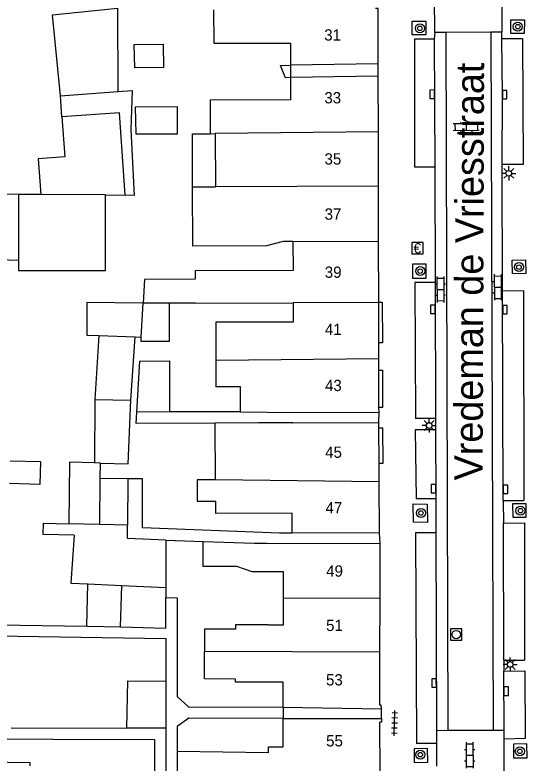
# Model space of a CAD drawing. Extents: x 132998 to 136004, y 396998 to 398512.
# Drawn here: x 133210.3 to 133255.7, y 397420.4 to 397486.6 of the extents above; entities that cross this region are included whole.
import ezdxf

# ---------------------------------------------------------------- set-up
doc = ezdxf.new("R2010")
doc.units = 0
for name, color, linetype in [('gg-afsc-erfafscheiding', 7, 'Continuous'), ('gg-anno-huisnummerreeks BGT', 7, 'Continuous'), ('gg-anno-openbare ruimte label', 7, 'Continuous'), ('gg-bbg-gedigitaliseerde bebouwing', 7, 'Continuous'), ('gg-bbg-gedigitaliseerde bebouwing onder overbouw', 7, 'Continuous'), ('gg-bbg-gedigitaliseerde bijgebouw', 7, 'Continuous'), ('gg-bbg-gedigitaliseerde overbouw', 7, 'Continuous'), ('gg-bbg-hoofdgebouw', 7, 'Continuous'), ('gg-bbg-luifel en loopbrug', 7, 'Continuous'), ('gg-bbg-onder overbouw', 7, 'Continuous'), ('gg-bbg-pand overbouw', 7, 'Continuous'), ('gg-bbg-tussenscheiding', 7, 'Continuous'), ('gg-knt-verharding', 7, 'Continuous'), ('gg-knt-verharding nz', 7, 'Continuous'), ('gt-grn-weggrens', 7, 'Continuous'), ('gt-symb-betaalautomaat', 7, 'Continuous'), ('gt-symb-boom', 7, 'Continuous'), ('gt-symb-klinker verharding', 7, 'Continuous'), ('gt-symb-kolk', 7, 'Continuous'), ('gt-symb-lichtmast', 7, 'Continuous'), ('gt-symb-rioolschacht', 7, 'Continuous'), ('gt-symb-tegel verharding', 7, 'Continuous')]:
    doc.layers.add(name, color=color, linetype=linetype)

# ---------------------------------------------------------------- blocks, each defined once
blk = doc.blocks.new('gt0-BOOM')
at = {"layer": 'gt-symb-boom'}
for radius in [0.4, 0.2]:
    blk.add_circle((0, 0), radius, dxfattribs=at)
blk = doc.blocks.new('gt0-KOLK')
at = {"layer": 'gt-symb-kolk'}
blk.add_lwpolyline([(0, 0), (0.375, 0), (0.375, 0.4), (-0.375, 0.4), (-0.375, 0), (0, 0)], dxfattribs=at)
blk = doc.blocks.new('gt0-KL1')
at = {"layer": 'gt-symb-klinker verharding'}
for p, q in [((-1.15, 0.3), (1.15, 0.3)), ((-1, -0.3), (-1, 0.3)), ((-0.5, 0.3), (-0.5, 0.45)), ((0, -0.3), (0, 0.3)), ((0.5, 0.3), (0.5, 0.45)), ((1, -0.3), (1, 0.3)), ((-1.15, -0.3), (1.15, -0.3)), ((-0.5, -0.45), (-0.5, -0.3)), ((0.5, -0.45), (0.5, -0.3))]:
    blk.add_line(p, q, dxfattribs=at)
blk = doc.blocks.new('gt0-BA')
at = {"layer": 'gt-symb-betaalautomaat'}
blk.add_lwpolyline([(-0.498, -0.507), (0.502, -0.507), (0.502, 0.493), (-0.498, 0.493)], close=True, dxfattribs=at)
blk.add_text('€', height=0.9, dxfattribs=at).set_placement((-0.357, -0.457))
blk = doc.blocks.new('gt0-LMAST')
at = {"layer": 'gt-symb-lichtmast'}
for p, q in [((-0.182, 0.173), (-0.447, 0.438)), ((-0.005, 0.246), (-0.005, 0.621)), ((0.172, 0.173), (0.437, 0.438)), ((-0.255, -0.004), (-0.63, -0.004)), ((-0.182, -0.181), (-0.447, -0.446)), ((-0.005, -0.254), (-0.005, -0.629)), ((0.437, -0.446), (0.172, -0.181)), ((0.245, -0.004), (0.62, -0.004))]:
    blk.add_line(p, q, dxfattribs=at)
blk.add_circle((-0.005, -0.004), 0.25, dxfattribs=at)
blk = doc.blocks.new('gt0-RS')
at = {"layer": 'gt-symb-rioolschacht'}
blk.add_lwpolyline([(-0.5, -0.5), (0.5, -0.5), (0.5, 0.5), (-0.5, 0.5)], close=True, dxfattribs=at)
blk.add_circle((0, 0), 0.375, dxfattribs=at)
blk = doc.blocks.new('gt0-TEG1')
at = {"layer": 'gt-symb-tegel verharding'}
for p, q in [((-1.125, 0), (1.125, 0)), ((-0.9, -0.25), (-0.9, 0.25)), ((-0.45, -0.25), (-0.45, 0.25)), ((0, -0.25), (0, 0.25)), ((0.45, -0.25), (0.45, 0.25)), ((0.9, -0.25), (0.9, 0.25))]:
    blk.add_line(p, q, dxfattribs=at)

msp = doc.modelspace()

# ---------------------------------------------------------------- linework, layer by layer
at = {"layer": 'gg-afsc-erfafscheiding'}
for p, q in [((133230.329, 397451.525), (133224.045, 397451.503)), ((133223.706, 397440.171), (133227.008, 397440.044)), ((133195.513, 397432.894), (133216.706, 397432.535)), ((133210.012, 397423.555), (133220.258, 397423.523)), ((133223.702, 397423.512), (133223.732, 397413.948))]:
    msp.add_line(p, q, dxfattribs=at)
for points in [[(133234.752, 397481.096), (133234.315, 397481.089), (133233.877, 397482.17), (133234.75, 397482.184)], [(133228.086, 397450.517), (133221.067, 397450.493), (133221.127, 397451.491)], [(133234.903, 397440.789), (133233.779, 397440.784), (133221.655, 397441.251), (133221.638, 397445.579), (133220.329, 397445.595)], [(133223.705, 397435.073), (133224.704, 397435.057), (133224.703, 397426.317), (133225.73, 397425.411), (133234.113, 397425.367)], [(133195.528, 397431.894), (133223.704, 397431.45), (133223.703, 397427.684)], [(133234.113, 397424.367), (133225.758, 397424.411), (133224.702, 397423.676), (133224.702, 397421.465)], [(133195.668, 397422.601), (133222.702, 397422.515), (133222.701, 397418.032)]]:
    msp.add_lwpolyline(points, dxfattribs=at)
at = {"layer": 'gg-bbg-gedigitaliseerde bebouwing'}
for p, q in [((133227.624, 397479.115), (133227.63, 397476.133)), ((133227.63, 397476.133), (133228.083, 397476.138)), ((133228.083, 397476.138), (133228.094, 397471.443)), ((133226.079, 397471.438), (133228.094, 397471.443)), ((133226.314, 397461.148), (133224.008, 397461.143)), ((133226.314, 397461.148), (133234.995, 397461.169)), ((133228.133, 397456.069), (133228.138, 397453.718)), ((133230.329, 397451.525), (133235.09, 397451.45)), ((133235.09, 397451.45), (133242.59, 397451.48)), ((133228.117, 397445.499), (133228.086, 397450.517)), ((133234.952, 397450.549), (133242.58, 397450.58)), ((133242.64, 397440.82), (133234.903, 397440.789)), ((133232.658, 397439.883), (133242.69, 397439.87)), ((133234.12, 397435.022), (133234.12, 397437.352)), ((133224.702, 397421.465), (133224.701, 397419.539)), ((133232.811, 397421.326), (133224.702, 397421.465))]:
    msp.add_line(p, q, dxfattribs=at)
for points in [[(133227.94, 397487.099), (133227.959, 397484.134), (133234.746, 397484.149), (133234.748, 397483.15), (133234.75, 397482.184)], [(133234.752, 397481.096), (133234.757, 397479.131), (133227.624, 397479.115)], [(133234.97, 397466.605), (133234.092, 397466.603), (133232.639, 397466.201), (133226.091, 397466.186), (133226.079, 397471.438)], [(133234.97, 397466.605), (133234.976, 397464.027), (133226.307, 397464.007), (133226.309, 397463.259)], [(133226.309, 397463.259), (133221.828, 397463.241), (133221.702, 397461.137)], [(133234.995, 397461.169), (133234.999, 397459.454), (133228.125, 397459.438), (133228.133, 397456.069)], [(133230.329, 397451.525), (133230.32, 397453.726), (133228.138, 397453.718)], [(133234.952, 397450.549), (133231.929, 397450.53), (133228.086, 397450.517)], [(133228.117, 397445.499), (133226.48, 397445.489), (133226.492, 397443.596), (133228.129, 397443.606)], [(133234.903, 397440.789), (133234.892, 397442.548), (133228.136, 397442.506), (133228.129, 397443.606)], [(133234.12, 397437.352), (133231.362, 397437.356), (133229.994, 397437.823), (133227.006, 397437.827), (133227.008, 397440.044)], [(133227.008, 397440.044), (133231.55, 397439.883), (133232.658, 397439.883)], [(133232.769, 397432.659), (133234.12, 397432.659), (133234.12, 397435.022)], [(133232.769, 397432.659), (133229.892, 397432.674), (133229.89, 397432.272), (133227.147, 397432.286), (133227.137, 397430.316)], [(133229.866, 397427.592), (133229.867, 397427.867), (133227.124, 397427.881), (133227.137, 397430.316)], [(133234.113, 397425.367), (133234.113, 397427.592), (133229.866, 397427.592)], [(133232.811, 397421.326), (133232.811, 397421.87), (133234.113, 397421.87), (133234.113, 397424.367)]]:
    msp.add_lwpolyline(points, dxfattribs=at)
at = {"layer": 'gg-bbg-gedigitaliseerde bebouwing onder overbouw'}
for p, q in [((133242.521, 397482.308), (133234.75, 397482.184)), ((133242.523, 397481.22), (133234.752, 397481.096))]:
    msp.add_line(p, q, dxfattribs=at)
at = {"layer": 'gg-bbg-gedigitaliseerde bijgebouw'}
for p, q in [((133212.63, 397470.743), (133210.66, 397470.747)), ((133218.376, 397470.731), (133220.108, 397470.694)), ((133217.786, 397458.263), (133220.981, 397458.148)), ((133220.981, 397458.148), (133221.523, 397458.128)), ((133224.045, 397451.503), (133221.127, 397451.491)), ((133217.917, 397446.988), (133217.376, 397447.003)), ((133217.903, 397445.608), (133217.917, 397446.988)), ((133220.329, 397445.595), (133217.903, 397445.608)), ((133220.329, 397445.595), (133220.307, 397441.473)), ((133223.706, 397440.171), (133223.705, 397435.977)), ((133216.801, 397436.28), (133219.798, 397436.148)), ((133219.705, 397432.485), (133219.798, 397436.148)), ((133223.705, 397435.977), (133223.705, 397435.073)), ((133223.703, 397427.684), (133223.702, 397423.512)), ((133223.702, 397423.512), (133220.258, 397423.523))]:
    msp.add_line(p, q, dxfattribs=at)
for points in [[(133224.749, 397476.125), (133224.742, 397478.503), (133221.004, 397478.488), (133221.042, 397476.11), (133224.749, 397476.125)], [(133220.108, 397470.694), (133219.592, 397477.978), (133214.503, 397477.617)], [(133214.503, 397477.617), (133214.754, 397474.074), (133212.405, 397473.907), (133212.63, 397470.743)], [(133210.66, 397470.747), (133206.364, 397470.882), (133206.182, 397465.075), (133210.66, 397464.935)], [(133210.66, 397464.935), (133210.66, 397464.035), (133218.376, 397464.035), (133218.376, 397470.731)], [(133221.702, 397461.137), (133216.707, 397461.185), (133216.719, 397458.301), (133217.786, 397458.263)], [(133224.008, 397461.143), (133224.008, 397457.734), (133221.523, 397457.734), (133221.523, 397458.128)], [(133221.127, 397451.491), (133221.396, 397456.004), (133224.027, 397456.029), (133224.045, 397451.503)], [(133209.926, 397447.19), (133212.595, 397447.122), (133212.543, 397445.09), (133209.866, 397445.17)], [(133217.376, 397447.003), (133215.165, 397447.062), (133215.109, 397441.604)], [(133215.598, 397440.597), (133212.853, 397440.663), (133212.877, 397441.653), (133215.109, 397441.604)], [(133223.706, 397440.171), (133220.301, 397440.302), (133220.307, 397441.473)], [(133215.598, 397440.597), (133215.282, 397436.346), (133216.801, 397436.28)], [(133219.705, 397432.485), (133223.704, 397432.383), (133223.705, 397435.073)], [(133220.258, 397423.523), (133220.33, 397427.72), (133223.703, 397427.684)], [(133205.812, 397420.574), (133211.655, 397420.489), (133211.651, 397420.189)]]:
    msp.add_lwpolyline(points, dxfattribs=at)
at = {"layer": 'gg-bbg-gedigitaliseerde overbouw'}
for p, q in [((133234.75, 397482.184), (133234.752, 397481.096)), ((133234.113, 397425.367), (133234.113, 397424.367))]:
    msp.add_line(p, q, dxfattribs=at)
at = {"layer": 'gg-bbg-hoofdgebouw'}
for p, q in [((133242.534, 397476.305), (133242.523, 397481.22)), ((133242.545, 397471.478), (133242.534, 397476.305)), ((133242.556, 397466.623), (133242.545, 397471.478)), ((133242.568, 397461.225), (133242.556, 397466.623)), ((133242.568, 397461.187), (133242.568, 397461.225)), ((133242.576, 397457.617), (133242.568, 397461.187)), ((133242.579, 397456.207), (133242.576, 397457.617)), ((133242.581, 397455.196), (133242.579, 397456.207)), ((133242.589, 397451.909), (133242.581, 397455.196)), ((133242.59, 397451.48), (133242.589, 397451.909)), ((133242.583, 397450.091), (133242.58, 397450.58)), ((133242.602, 397446.947), (133242.583, 397450.091)), ((133242.612, 397445.32), (133242.602, 397446.947)), ((133242.64, 397440.82), (133242.612, 397445.32)), ((133242.683, 397434.99), (133242.69, 397439.87)), ((133242.676, 397430.257), (133242.683, 397434.99)), ((133242.673, 397425.556), (133242.676, 397430.257)), ((133242.692, 397419.472), (133242.677, 397424.045))]:
    msp.add_line(p, q, dxfattribs=at)
for points in [[(133242.521, 397482.308), (133242.51, 397487.21), (133242.281, 397487.208)], [(133242.796, 397425.228), (133242.792, 397425.558), (133242.673, 397425.556)], [(133242.802, 397424.377), (133242.806, 397424.046), (133242.677, 397424.045)]]:
    msp.add_lwpolyline(points, dxfattribs=at)
at = {"layer": 'gg-bbg-luifel en loopbrug'}
for p, q in [((133214.37, 397479.497), (133219.45, 397479.857)), ((133214.503, 397477.617), (133214.37, 397479.497)), ((133217.786, 397458.263), (133217.409, 397452.614)), ((133220.606, 397452.549), (133220.981, 397458.148)), ((133217.409, 397452.614), (133217.376, 397447.003)), ((133217.409, 397452.614), (133220.606, 397452.549)), ((133220.382, 397446.922), (133220.606, 397452.549)), ((133217.917, 397446.988), (133220.382, 397446.922)), ((133216.706, 397432.535), (133216.801, 397436.28)), ((133216.706, 397432.535), (133219.705, 397432.485))]:
    msp.add_line(p, q, dxfattribs=at)
for points in [[(133214.37, 397479.497), (133213.661, 397486.66), (133219.412, 397487.229), (133219.45, 397479.857)], [(133220.917, 397484.028), (133223.473, 397484.069), (133223.505, 397482.004), (133220.949, 397481.963), (133220.917, 397484.028)], [(133219.45, 397479.857), (133220.732, 397479.948), (133220.6, 397476.511), (133220.902, 397470.677), (133220.108, 397470.694)], [(133226.079, 397471.438), (133226.068, 397476.115), (133227.63, 397476.133)]]:
    msp.add_lwpolyline(points, dxfattribs=at)
at = {"layer": 'gg-bbg-onder overbouw'}
for p, q in [((133234.113, 397425.367), (133242.796, 397425.228)), ((133234.113, 397424.367), (133242.802, 397424.377))]:
    msp.add_line(p, q, dxfattribs=at)
at = {"layer": 'gg-bbg-pand overbouw'}
for p, q in [((133242.523, 397481.22), (133242.521, 397482.308)), ((133242.802, 397424.377), (133242.796, 397425.228))]:
    msp.add_line(p, q, dxfattribs=at)
at = {"layer": 'gg-bbg-tussenscheiding'}
for p, q in [((133242.534, 397476.305), (133228.083, 397476.138)), ((133242.545, 397471.478), (133228.094, 397471.443)), ((133210.66, 397470.747), (133210.66, 397464.935)), ((133218.376, 397470.731), (133212.63, 397470.743)), ((133234.97, 397466.605), (133242.556, 397466.623)), ((133221.523, 397458.128), (133221.702, 397461.137)), ((133224.008, 397461.143), (133221.702, 397461.137)), ((133242.568, 397461.187), (133234.995, 397461.169)), ((133242.579, 397456.207), (133228.133, 397456.069)), ((133217.861, 397441.532), (133217.903, 397445.608)), ((133242.612, 397445.32), (133228.117, 397445.499)), ((133217.861, 397441.532), (133215.109, 397441.604)), ((133220.307, 397441.473), (133217.861, 397441.532)), ((133219.798, 397436.148), (133223.705, 397435.977)), ((133242.683, 397434.99), (133234.12, 397435.022)), ((133242.676, 397430.257), (133227.137, 397430.316))]:
    msp.add_line(p, q, dxfattribs=at)
at = {"layer": 'gg-knt-verharding'}
for p, q in [((133247.52, 397485.08), (133247.497, 397492.427)), ((133253.459, 397490.87), (133253.475, 397485.116)), ((133247.52, 397485.08), (133247.487, 397484.499)), ((133248.52, 397485.086), (133247.52, 397485.08)), ((133252.497, 397485.11), (133248.52, 397485.086)), ((133253.475, 397485.116), (133252.497, 397485.11)), ((133253.472, 397484.553), (133253.475, 397485.116)), ((133247.523, 397473.194), (133247.555, 397462.964)), ((133253.542, 397462.226), (133253.507, 397473.409)), ((133247.593, 397450.918), (133245.837, 397450.912)), ((133247.593, 397450.918), (133247.596, 397449.918)), ((133247.596, 397449.918), (133245.805, 397449.912)), ((133245.805, 397449.912), (133245.87, 397443.812)), ((133247.616, 397443.818), (133245.87, 397443.812)), ((133247.616, 397443.818), (133247.625, 397440.818)), ((133253.601, 397443.676), (133255.428, 397443.682)), ((133253.601, 397443.676), (133253.608, 397441.676)), ((133253.608, 397441.676), (133255.469, 397441.682)), ((133255.469, 397441.682), (133255.49, 397429.532)), ((133247.625, 397440.818), (133245.82, 397440.812)), ((133245.82, 397440.812), (133245.908, 397422.163)), ((133253.646, 397429.526), (133255.49, 397429.532)), ((133253.646, 397429.526), (133253.649, 397428.576)), ((133253.649, 397428.576), (133255.492, 397428.582)), ((133248.68, 397423.301), (133247.68, 397423.298)), ((133247.68, 397423.298), (133247.684, 397422.169)), ((133252.696, 397423.314), (133248.68, 397423.301)), ((133253.666, 397423.317), (133252.696, 397423.314)), ((133253.668, 397422.537), (133253.666, 397423.317)), ((133253.678, 397419.297), (133253.668, 397422.537)), ((133247.684, 397422.169), (133245.908, 397422.163)), ((133247.684, 397422.169), (133247.691, 397420.169))]:
    msp.add_line(p, q, dxfattribs=at)
for points in [[(133245.531, 397484.882), (133245.531, 397486.09), (133246.731, 397486.09), (133246.731, 397484.882), (133245.531, 397484.882)], [(133254.261, 397485.012), (133254.265, 397486.222), (133255.465, 397486.218), (133255.461, 397485.008), (133254.261, 397485.012)], [(133247.487, 397484.499), (133245.73, 397484.5), (133245.738, 397473.191), (133247.523, 397473.194)], [(133253.472, 397484.553), (133255.288, 397484.551), (133255.346, 397473.406), (133253.507, 397473.409)], [(133245.565, 397464.579), (133245.568, 397463.339), (133246.768, 397463.342), (133246.765, 397464.582), (133245.565, 397464.579)], [(133254.381, 397464.945), (133255.58, 397464.969), (133255.605, 397463.768), (133254.405, 397463.744), (133254.381, 397464.945)], [(133247.555, 397462.964), (133245.754, 397462.959), (133245.837, 397450.912)], [(133253.542, 397462.226), (133255.389, 397462.266), (133255.428, 397443.682)], [(133242.568, 397461.225), (133242.88, 397461.225), (133242.896, 397457.618), (133242.576, 397457.617)], [(133242.581, 397455.196), (133242.889, 397455.197), (133242.909, 397451.91), (133242.589, 397451.909)], [(133242.583, 397450.091), (133242.902, 397450.095), (133242.916, 397446.949), (133242.602, 397446.947)], [(133245.629, 397443.373), (133246.868, 397443.356), (133246.871, 397441.733), (133245.632, 397441.749), (133245.629, 397443.373)], [(133254.428, 397443.382), (133254.429, 397442.183), (133255.629, 397442.184), (133255.628, 397443.383), (133254.428, 397443.382)], [(133255.492, 397428.582), (133255.546, 397422.603), (133253.668, 397422.537)], [(133245.698, 397421.689), (133245.717, 397420.495), (133246.916, 397420.514), (133246.898, 397421.708), (133245.698, 397421.689)], [(133254.491, 397422.109), (133254.503, 397420.885), (133255.703, 397420.897), (133255.691, 397422.121), (133254.491, 397422.109)]]:
    msp.add_lwpolyline(points, dxfattribs=at)
at = {"layer": 'gg-knt-verharding nz'}
for p, q in [((133248.52, 397485.086), (133248.68, 397423.301)), ((133252.497, 397485.11), (133252.696, 397423.314)), ((133247.487, 397484.499), (133247.523, 397473.194)), ((133247.555, 397462.964), (133247.593, 397450.918)), ((133253.601, 397443.676), (133253.542, 397462.226)), ((133247.596, 397449.918), (133247.616, 397443.818)), ((133253.646, 397429.526), (133253.608, 397441.676)), ((133247.625, 397440.818), (133247.68, 397423.298)), ((133253.666, 397423.317), (133253.649, 397428.576))]:
    msp.add_line(p, q, dxfattribs=at)
msp.add_lwpolyline([(133253.507, 397473.409), (133253.517, 397479.582), (133253.472, 397484.553)], dxfattribs=at)
at = {"layer": 'gt-grn-weggrens'}
for p, q in [((133242.58, 397450.58), (133242.59, 397451.48)), ((133242.69, 397439.87), (133242.64, 397440.82))]:
    msp.add_line(p, q, dxfattribs=at)

# ---------------------------------------------------------------- block references
at = {"layer": 'gt-symb-betaalautomaat'}
msp.add_blockref('gt0-BA', (133246, 397466), dxfattribs=at)
at = {"layer": 'gt-symb-boom'}
for p in [(133246.208, 397485.461), (133254.884, 397485.611), (133254.983, 397464.326), (133246.241, 397463.972), (133246.302, 397442.557), (133255.122, 397442.766), (133246.25, 397421.18), (133255.065, 397421.473)]:
    msp.add_blockref('gt0-BOOM', p, dxfattribs=at)
at = {"layer": 'gt-symb-klinker verharding'}
for p, rotation in [((133250.32, 397476.708), -179.59893609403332), ((133248.025, 397462.356), -89.82811317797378), ((133253.103, 397462.539), -89.82811317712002), ((133250.616, 397421.128), -89.82811317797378)]:
    msp.add_blockref('gt0-KL1', p, dxfattribs=dict(at, rotation=rotation))
at = {"layer": 'gt-symb-kolk'}
for p, rotation in [((133247.503, 397479.627), 90.22918189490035), ((133253.517, 397479.582), -90.08876803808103), ((133247.563, 397460.59), 90.17188682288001), ((133253.547, 397460.56), -89.82811317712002), ((133247.613, 397444.71), 90.17188682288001), ((133253.598, 397444.649), -89.82811317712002), ((133247.667, 397427.51), 90.17188682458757), ((133253.652, 397426.79), -89.82811317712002)]:
    msp.add_blockref('gt0-KOLK', p, dxfattribs=dict(at, rotation=rotation))
at = {"layer": 'gt-symb-lichtmast', "rotation": 90}
for p in [(133254.079, 397472.63), (133247.035, 397450.307), (133254.207, 397429.161)]:
    msp.add_blockref('gt0-LMAST', p, dxfattribs=at)
at = {"layer": 'gt-symb-rioolschacht'}
msp.add_blockref('gt0-RS', (133249.432, 397431.801), dxfattribs=at)
at = {"layer": 'gt-symb-tegel verharding', "rotation": 88.39613722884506}
msp.add_blockref('gt0-TEG1', (133243.967, 397423.968), dxfattribs=at)

# ---------------------------------------------------------------- texts
at = {"layer": 'gg-anno-huisnummerreeks BGT'}
for s, rotation, p in [('31', 0.1, (133237.739, 397484.374)), ('33', 0.1, (133237.751, 397478.815)), ('35', 0.1, (133237.763, 397473.4)), ('37', 0.1, (133237.775, 397468.519)), ('39', 0.1, (133237.786, 397463.377)), ('41', 0.1, (133237.797, 397458.313)), ('43', 0.1, (133237.808, 397453.352)), ('45', 0.3, (133237.822, 397447.44)), ('47', 0.3, (133237.852, 397442.519)), ('49', 359.9, (133237.909, 397436.929)), ('51', 359.9, (133237.902, 397432.12)), ('53', 359.9, (133237.897, 397427.303)), ('55', 0.2, (133237.906, 397421.899))]:
    msp.add_text(s, height=1, rotation=rotation, dxfattribs=at).set_placement(p)
at = {"layer": 'gg-anno-openbare ruimte label'}
msp.add_text('Vredeman de Vriesstraat', height=2.5, rotation=89.8, dxfattribs=at).set_placement((133251.767, 397445.441))

doc.saveas('drawing.dxf')
